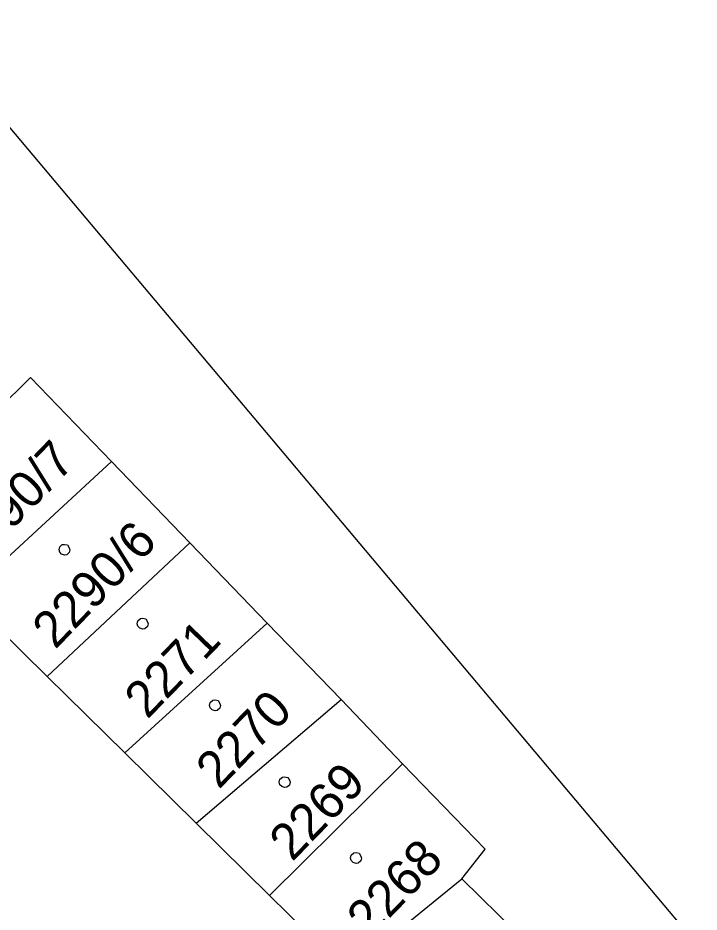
# Model space of a CAD drawing. Extents: x -528274 to -527531, y -1079304 to -1078580.
# Drawn here: x -527922.63 to -527901.28, y -1078881.94 to -1078853.89 of the extents above; entities that cross this region are included whole.
import ezdxf

# ---------------------------------------------------------------- set-up
doc = ezdxf.new("R2010")
doc.units = 0
doc.layers.add('katastrální mapa', color=7, linetype='Continuous')

msp = doc.modelspace()

# ---------------------------------------------------------------- linework, layer by layer
at = {"layer": 'katastrální mapa'}
for p, q in [((-527929.39, -1078849.6), (-527890.85, -1078895.43)), ((-527922.23, -1078865.17), (-527926.71, -1078869.56)), ((-527919.7, -1078867.8), (-527922.23, -1078865.17)), ((-527924.27, -1078872.03), (-527919.7, -1078867.8)), ((-527917.24, -1078870.35), (-527919.7, -1078867.8)), ((-527921.71, -1078874.55), (-527917.24, -1078870.35)), ((-527914.82, -1078872.87), (-527917.24, -1078870.35)), ((-527924.27, -1078872.03), (-527921.71, -1078874.55)), ((-527919.28, -1078876.94), (-527914.82, -1078872.87)), ((-527912.5, -1078875.27), (-527914.82, -1078872.87)), ((-527921.71, -1078874.55), (-527919.28, -1078876.94)), ((-527917.04, -1078879.14), (-527912.5, -1078875.27)), ((-527910.57, -1078877.28), (-527912.5, -1078875.27)), ((-527919.28, -1078876.94), (-527917.04, -1078879.14)), ((-527914.74, -1078881.41), (-527910.57, -1078877.28)), ((-527907.98, -1078879.96), (-527910.57, -1078877.28)), ((-527917.04, -1078879.14), (-527914.74, -1078881.41)), ((-527908.71, -1078880.89), (-527907.98, -1078879.96)), ((-527912.31, -1078883.81), (-527908.71, -1078880.89)), ((-527908.71, -1078880.89), (-527906.69, -1078882.87)), ((-527914.74, -1078881.41), (-527912.31, -1078883.81))]:
    msp.add_line(p, q, dxfattribs=at)
for points in [[(-527921.17, -1078870.4), (-527921.07, -1078870.42), (-527921.02, -1078870.51), (-527921, -1078870.57), (-527921.02, -1078870.66), (-527921.1, -1078870.73), (-527921.17, -1078870.74), (-527921.26, -1078870.71), (-527921.32, -1078870.65), (-527921.34, -1078870.57), (-527921.32, -1078870.48), (-527921.24, -1078870.41)], [(-527918.72, -1078872.72), (-527918.62, -1078872.74), (-527918.57, -1078872.83), (-527918.55, -1078872.89), (-527918.57, -1078872.98), (-527918.65, -1078873.05), (-527918.72, -1078873.06), (-527918.81, -1078873.03), (-527918.87, -1078872.97), (-527918.89, -1078872.89), (-527918.87, -1078872.8), (-527918.79, -1078872.73)], [(-527916.45, -1078875.28), (-527916.35, -1078875.3), (-527916.3, -1078875.39), (-527916.28, -1078875.45), (-527916.3, -1078875.54), (-527916.38, -1078875.61), (-527916.45, -1078875.62), (-527916.54, -1078875.59), (-527916.6, -1078875.53), (-527916.62, -1078875.45), (-527916.6, -1078875.36), (-527916.52, -1078875.29)], [(-527914.27, -1078877.69), (-527914.17, -1078877.71), (-527914.12, -1078877.8), (-527914.1, -1078877.86), (-527914.12, -1078877.95), (-527914.2, -1078878.02), (-527914.27, -1078878.03), (-527914.36, -1078878), (-527914.42, -1078877.94), (-527914.44, -1078877.86), (-527914.42, -1078877.77), (-527914.34, -1078877.7)], [(-527912.03, -1078880.07), (-527911.93, -1078880.09), (-527911.88, -1078880.18), (-527911.86, -1078880.24), (-527911.88, -1078880.33), (-527911.96, -1078880.4), (-527912.03, -1078880.41), (-527912.12, -1078880.38), (-527912.18, -1078880.32), (-527912.2, -1078880.24), (-527912.18, -1078880.15), (-527912.1, -1078880.08)]]:
    msp.add_lwpolyline(points, close=True, dxfattribs=at)

# ---------------------------------------------------------------- texts
for s, p in [('2290/7', (-527924.019, -1078871.196)), ('2290/6', (-527921.459, -1078873.716)), ('2271', (-527918.569, -1078875.906)), ('2270', (-527916.329, -1078878.106)), ('2269', (-527914.029, -1078880.376)), ('2268', (-527911.599, -1078882.776))]:
    msp.add_text(s, height=1.14, rotation=45.9512, dxfattribs=at).set_placement(p)

doc.saveas('drawing.dxf')
